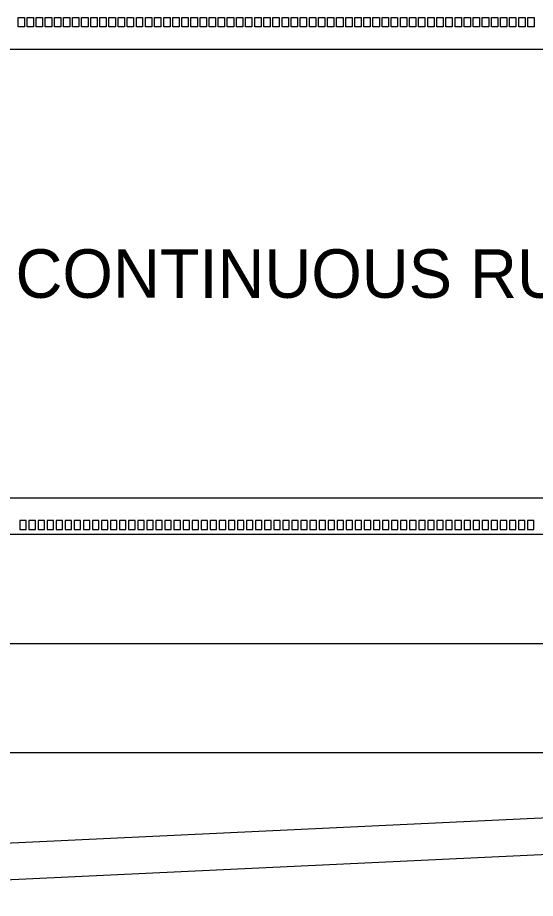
# Model space of a CAD drawing. Extents: x 49991.4 to 50021, y 49987.6 to 50011.4.
# Drawn here: x 50009.271 to 50009.911, y 49989.406 to 49990.494 of the extents above; entities that cross this region are included whole.
import ezdxf

# ---------------------------------------------------------------- set-up
doc = ezdxf.new("R2010")
doc.units = 0
doc.layers.add('Level 1', color=7, linetype='Continuous')
doc.layers.add('Level 2', color=7, linetype='Continuous')

msp = doc.modelspace()

# ---------------------------------------------------------------- linework, layer by layer
at = {"layer": 'Level 1'}
for p, q in [((50012.4393, 49990.4548), (50005.9012, 49990.4548)), ((50005.9009, 49989.9006), (50012.4391, 49989.9007)), ((50005.9009, 49989.8556), (50012.4391, 49989.8557)), ((50005.9009, 49989.7206), (50012.4391, 49989.7207)), ((50005.9009, 49989.5856), (50012.4391, 49989.5857)), ((50008.7675, 49989.4506), (50011.625, 49989.5857)), ((50008.7679, 49989.4055), (50010.1995, 49989.473))]:
    msp.add_line(p, q, dxfattribs=at)
for points in [[(50009.2797, 49990.4828), (50009.2719, 49990.4828), (50009.2719, 49990.494), (50009.2797, 49990.494)], [(50009.2909, 49990.4828), (50009.2831, 49990.4828), (50009.2831, 49990.494), (50009.2909, 49990.494)], [(50009.3022, 49990.4828), (50009.2943, 49990.4828), (50009.2943, 49990.494), (50009.3022, 49990.494)], [(50009.3135, 49990.4828), (50009.3055, 49990.4828), (50009.3055, 49990.494), (50009.3135, 49990.494)], [(50009.3247, 49990.4828), (50009.3169, 49990.4828), (50009.3169, 49990.494), (50009.3247, 49990.494)], [(50009.3359, 49990.4828), (50009.3281, 49990.4828), (50009.3281, 49990.494), (50009.3359, 49990.494)], [(50009.3472, 49990.4828), (50009.3393, 49990.4828), (50009.3393, 49990.494), (50009.3472, 49990.494)], [(50009.3585, 49990.4828), (50009.3505, 49990.4828), (50009.3505, 49990.494), (50009.3585, 49990.494)], [(50009.3697, 49990.4828), (50009.3619, 49990.4828), (50009.3619, 49990.494), (50009.3697, 49990.494)], [(50009.3809, 49990.4828), (50009.3731, 49990.4828), (50009.3731, 49990.494), (50009.3809, 49990.494)], [(50009.3922, 49990.4828), (50009.3843, 49990.4828), (50009.3843, 49990.494), (50009.3922, 49990.494)], [(50009.4035, 49990.4828), (50009.3955, 49990.4828), (50009.3955, 49990.494), (50009.4035, 49990.494)], [(50009.4147, 49990.4828), (50009.4069, 49990.4828), (50009.4069, 49990.494), (50009.4147, 49990.494)], [(50009.4259, 49990.4828), (50009.4181, 49990.4828), (50009.4181, 49990.494), (50009.4259, 49990.494)], [(50009.4372, 49990.4828), (50009.4293, 49990.4828), (50009.4293, 49990.494), (50009.4372, 49990.494)], [(50009.4485, 49990.4828), (50009.4405, 49990.4828), (50009.4405, 49990.494), (50009.4485, 49990.494)], [(50009.4597, 49990.4828), (50009.4519, 49990.4828), (50009.4519, 49990.494), (50009.4597, 49990.494)], [(50009.4709, 49990.4828), (50009.4631, 49990.4828), (50009.4631, 49990.494), (50009.4709, 49990.494)], [(50009.4822, 49990.4828), (50009.4743, 49990.4828), (50009.4743, 49990.494), (50009.4822, 49990.494)], [(50009.4935, 49990.4828), (50009.4855, 49990.4828), (50009.4855, 49990.494), (50009.4935, 49990.494)], [(50009.5047, 49990.4828), (50009.4969, 49990.4828), (50009.4969, 49990.494), (50009.5047, 49990.494)], [(50009.5159, 49990.4828), (50009.5081, 49990.4828), (50009.5081, 49990.494), (50009.5159, 49990.494)], [(50009.5272, 49990.4828), (50009.5193, 49990.4828), (50009.5193, 49990.494), (50009.5272, 49990.494)], [(50009.5385, 49990.4828), (50009.5305, 49990.4828), (50009.5305, 49990.494), (50009.5385, 49990.494)], [(50009.5497, 49990.4828), (50009.5419, 49990.4828), (50009.5419, 49990.494), (50009.5497, 49990.494)], [(50009.5609, 49990.4828), (50009.5531, 49990.4828), (50009.5531, 49990.494), (50009.5609, 49990.494)], [(50009.5722, 49990.4828), (50009.5643, 49990.4828), (50009.5643, 49990.494), (50009.5722, 49990.494)], [(50009.5835, 49990.4828), (50009.5755, 49990.4828), (50009.5755, 49990.494), (50009.5835, 49990.494)], [(50009.5947, 49990.4828), (50009.5869, 49990.4828), (50009.5869, 49990.494), (50009.5947, 49990.494)], [(50009.6059, 49990.4828), (50009.5981, 49990.4828), (50009.5981, 49990.494), (50009.6059, 49990.494)], [(50009.6172, 49990.4828), (50009.6093, 49990.4828), (50009.6093, 49990.494), (50009.6172, 49990.494)], [(50009.6285, 49990.4828), (50009.6205, 49990.4828), (50009.6205, 49990.494), (50009.6285, 49990.494)], [(50009.6397, 49990.4828), (50009.6319, 49990.4828), (50009.6319, 49990.494), (50009.6397, 49990.494)], [(50009.6509, 49990.4828), (50009.6431, 49990.4828), (50009.6431, 49990.494), (50009.6509, 49990.494)], [(50009.6622, 49990.4828), (50009.6543, 49990.4828), (50009.6543, 49990.494), (50009.6622, 49990.494)], [(50009.6735, 49990.4828), (50009.6655, 49990.4828), (50009.6655, 49990.494), (50009.6735, 49990.494)], [(50009.6847, 49990.4828), (50009.6769, 49990.4828), (50009.6769, 49990.494), (50009.6847, 49990.494)], [(50009.6959, 49990.4828), (50009.6881, 49990.4828), (50009.6881, 49990.494), (50009.6959, 49990.494)], [(50009.7072, 49990.4828), (50009.6993, 49990.4828), (50009.6993, 49990.494), (50009.7072, 49990.494)], [(50009.7185, 49990.4828), (50009.7105, 49990.4828), (50009.7105, 49990.494), (50009.7185, 49990.494)], [(50009.7297, 49990.4828), (50009.7219, 49990.4828), (50009.7219, 49990.494), (50009.7297, 49990.494)], [(50009.7409, 49990.4828), (50009.7331, 49990.4828), (50009.7331, 49990.494), (50009.7409, 49990.494)], [(50009.7522, 49990.4828), (50009.7443, 49990.4828), (50009.7443, 49990.494), (50009.7522, 49990.494)], [(50009.7635, 49990.4828), (50009.7555, 49990.4828), (50009.7555, 49990.494), (50009.7635, 49990.494)], [(50009.7747, 49990.4828), (50009.7669, 49990.4828), (50009.7669, 49990.494), (50009.7747, 49990.494)], [(50009.7859, 49990.4828), (50009.7781, 49990.4828), (50009.7781, 49990.494), (50009.7859, 49990.494)], [(50009.7972, 49990.4828), (50009.7893, 49990.4828), (50009.7893, 49990.494), (50009.7972, 49990.494)], [(50009.8085, 49990.4828), (50009.8005, 49990.4828), (50009.8005, 49990.494), (50009.8085, 49990.494)], [(50009.8197, 49990.4828), (50009.8119, 49990.4828), (50009.8119, 49990.494), (50009.8197, 49990.494)], [(50009.8309, 49990.4828), (50009.8231, 49990.4828), (50009.8231, 49990.494), (50009.8309, 49990.494)], [(50009.8422, 49990.4828), (50009.8343, 49990.4828), (50009.8343, 49990.494), (50009.8422, 49990.494)], [(50009.8535, 49990.4828), (50009.8455, 49990.4828), (50009.8455, 49990.494), (50009.8535, 49990.494)], [(50009.8647, 49990.4828), (50009.8569, 49990.4828), (50009.8569, 49990.494), (50009.8647, 49990.494)], [(50009.8759, 49990.4828), (50009.8681, 49990.4828), (50009.8681, 49990.494), (50009.8759, 49990.494)], [(50009.8872, 49990.4828), (50009.8793, 49990.4828), (50009.8793, 49990.494), (50009.8872, 49990.494)], [(50009.8985, 49990.4828), (50009.8905, 49990.4828), (50009.8905, 49990.494), (50009.8985, 49990.494)], [(50009.9097, 49990.4828), (50009.9019, 49990.4828), (50009.9019, 49990.494), (50009.9097, 49990.494)], [(50009.2821, 49989.8727), (50009.2742, 49989.8727), (50009.2742, 49989.8615), (50009.2821, 49989.8615)], [(50009.2933, 49989.8727), (50009.2854, 49989.8727), (50009.2854, 49989.8615), (50009.2933, 49989.8615)], [(50009.3045, 49989.8727), (50009.2966, 49989.8727), (50009.2966, 49989.8615), (50009.3045, 49989.8615)], [(50009.3157, 49989.8727), (50009.3078, 49989.8727), (50009.3078, 49989.8615), (50009.3157, 49989.8615)], [(50009.3269, 49989.8727), (50009.319, 49989.8727), (50009.319, 49989.8615), (50009.3269, 49989.8615)], [(50009.3381, 49989.8727), (50009.3302, 49989.8727), (50009.3302, 49989.8615), (50009.3381, 49989.8615)], [(50009.3493, 49989.8727), (50009.3414, 49989.8727), (50009.3414, 49989.8615), (50009.3493, 49989.8615)], [(50009.3605, 49989.8727), (50009.3526, 49989.8727), (50009.3526, 49989.8615), (50009.3605, 49989.8615)], [(50009.3717, 49989.8727), (50009.3638, 49989.8727), (50009.3638, 49989.8615), (50009.3717, 49989.8615)], [(50009.3829, 49989.8727), (50009.375, 49989.8727), (50009.375, 49989.8615), (50009.3829, 49989.8615)], [(50009.3941, 49989.8727), (50009.3862, 49989.8727), (50009.3862, 49989.8615), (50009.3941, 49989.8615)], [(50009.4053, 49989.8727), (50009.3974, 49989.8727), (50009.3974, 49989.8615), (50009.4053, 49989.8615)], [(50009.4165, 49989.8727), (50009.4086, 49989.8727), (50009.4086, 49989.8615), (50009.4165, 49989.8615)], [(50009.4277, 49989.8727), (50009.4198, 49989.8727), (50009.4198, 49989.8615), (50009.4277, 49989.8615)], [(50009.4389, 49989.8727), (50009.431, 49989.8727), (50009.431, 49989.8615), (50009.4389, 49989.8615)], [(50009.4501, 49989.8727), (50009.4422, 49989.8727), (50009.4422, 49989.8615), (50009.4501, 49989.8615)], [(50009.4613, 49989.8727), (50009.4534, 49989.8727), (50009.4534, 49989.8615), (50009.4613, 49989.8615)], [(50009.4725, 49989.8727), (50009.4646, 49989.8727), (50009.4646, 49989.8615), (50009.4725, 49989.8615)], [(50009.4837, 49989.8727), (50009.4758, 49989.8727), (50009.4758, 49989.8615), (50009.4837, 49989.8615)], [(50009.4949, 49989.8727), (50009.487, 49989.8727), (50009.487, 49989.8615), (50009.4949, 49989.8615)], [(50009.5061, 49989.8727), (50009.4982, 49989.8727), (50009.4982, 49989.8615), (50009.5061, 49989.8615)], [(50009.5173, 49989.8727), (50009.5094, 49989.8727), (50009.5094, 49989.8615), (50009.5173, 49989.8615)], [(50009.5285, 49989.8727), (50009.5206, 49989.8727), (50009.5206, 49989.8615), (50009.5285, 49989.8615)], [(50009.5397, 49989.8727), (50009.5318, 49989.8727), (50009.5318, 49989.8615), (50009.5397, 49989.8615)], [(50009.5509, 49989.8727), (50009.543, 49989.8727), (50009.543, 49989.8615), (50009.5509, 49989.8615)], [(50009.5621, 49989.8727), (50009.5542, 49989.8727), (50009.5542, 49989.8615), (50009.5621, 49989.8615)], [(50009.5733, 49989.8727), (50009.5654, 49989.8727), (50009.5654, 49989.8615), (50009.5733, 49989.8615)], [(50009.5845, 49989.8727), (50009.5766, 49989.8727), (50009.5766, 49989.8615), (50009.5845, 49989.8615)], [(50009.5957, 49989.8727), (50009.5878, 49989.8727), (50009.5878, 49989.8615), (50009.5957, 49989.8615)], [(50009.6069, 49989.8727), (50009.599, 49989.8727), (50009.599, 49989.8615), (50009.6069, 49989.8615)], [(50009.6181, 49989.8727), (50009.6102, 49989.8727), (50009.6102, 49989.8615), (50009.6181, 49989.8615)], [(50009.6293, 49989.8727), (50009.6214, 49989.8727), (50009.6214, 49989.8615), (50009.6293, 49989.8615)], [(50009.6405, 49989.8727), (50009.6326, 49989.8727), (50009.6326, 49989.8615), (50009.6405, 49989.8615)], [(50009.6517, 49989.8727), (50009.6438, 49989.8727), (50009.6438, 49989.8615), (50009.6517, 49989.8615)], [(50009.6629, 49989.8727), (50009.655, 49989.8727), (50009.655, 49989.8615), (50009.6629, 49989.8615)], [(50009.6741, 49989.8727), (50009.6662, 49989.8727), (50009.6662, 49989.8615), (50009.6741, 49989.8615)], [(50009.6853, 49989.8727), (50009.6774, 49989.8727), (50009.6774, 49989.8615), (50009.6853, 49989.8615)], [(50009.6965, 49989.8727), (50009.6886, 49989.8727), (50009.6886, 49989.8615), (50009.6965, 49989.8615)], [(50009.7077, 49989.8727), (50009.6998, 49989.8727), (50009.6998, 49989.8615), (50009.7077, 49989.8615)], [(50009.7189, 49989.8727), (50009.711, 49989.8727), (50009.711, 49989.8615), (50009.7189, 49989.8615)], [(50009.7301, 49989.8727), (50009.7222, 49989.8727), (50009.7222, 49989.8615), (50009.7301, 49989.8615)], [(50009.7413, 49989.8727), (50009.7334, 49989.8727), (50009.7334, 49989.8615), (50009.7413, 49989.8615)], [(50009.7525, 49989.8727), (50009.7446, 49989.8727), (50009.7446, 49989.8615), (50009.7525, 49989.8615)], [(50009.7637, 49989.8727), (50009.7558, 49989.8727), (50009.7558, 49989.8615), (50009.7637, 49989.8615)], [(50009.7749, 49989.8727), (50009.767, 49989.8727), (50009.767, 49989.8615), (50009.7749, 49989.8615)], [(50009.7861, 49989.8727), (50009.7782, 49989.8727), (50009.7782, 49989.8615), (50009.7861, 49989.8615)], [(50009.7973, 49989.8727), (50009.7894, 49989.8727), (50009.7894, 49989.8615), (50009.7973, 49989.8615)], [(50009.8085, 49989.8727), (50009.8006, 49989.8727), (50009.8006, 49989.8615), (50009.8085, 49989.8615)], [(50009.8197, 49989.8727), (50009.8118, 49989.8727), (50009.8118, 49989.8615), (50009.8197, 49989.8615)], [(50009.8309, 49989.8727), (50009.823, 49989.8727), (50009.823, 49989.8615), (50009.8309, 49989.8615)], [(50009.8421, 49989.8727), (50009.8342, 49989.8727), (50009.8342, 49989.8615), (50009.8421, 49989.8615)], [(50009.8533, 49989.8727), (50009.8454, 49989.8727), (50009.8454, 49989.8615), (50009.8533, 49989.8615)], [(50009.8645, 49989.8727), (50009.8566, 49989.8727), (50009.8566, 49989.8615), (50009.8645, 49989.8615)], [(50009.8757, 49989.8727), (50009.8678, 49989.8727), (50009.8678, 49989.8615), (50009.8757, 49989.8615)], [(50009.8869, 49989.8727), (50009.879, 49989.8727), (50009.879, 49989.8615), (50009.8869, 49989.8615)], [(50009.8981, 49989.8727), (50009.8902, 49989.8727), (50009.8902, 49989.8615), (50009.8981, 49989.8615)], [(50009.9093, 49989.8727), (50009.9014, 49989.8727), (50009.9014, 49989.8615), (50009.9093, 49989.8615)]]:
    msp.add_lwpolyline(points, close=True, dxfattribs=at)

# ---------------------------------------------------------------- texts
at = {"layer": 'Level 2'}
msp.add_text('CONTINUOUS RUMBLE STRIPS', height=0.06, rotation=359.9999, dxfattribs=at).set_placement((50009.2688, 49990.1477))

doc.saveas('drawing.dxf')
